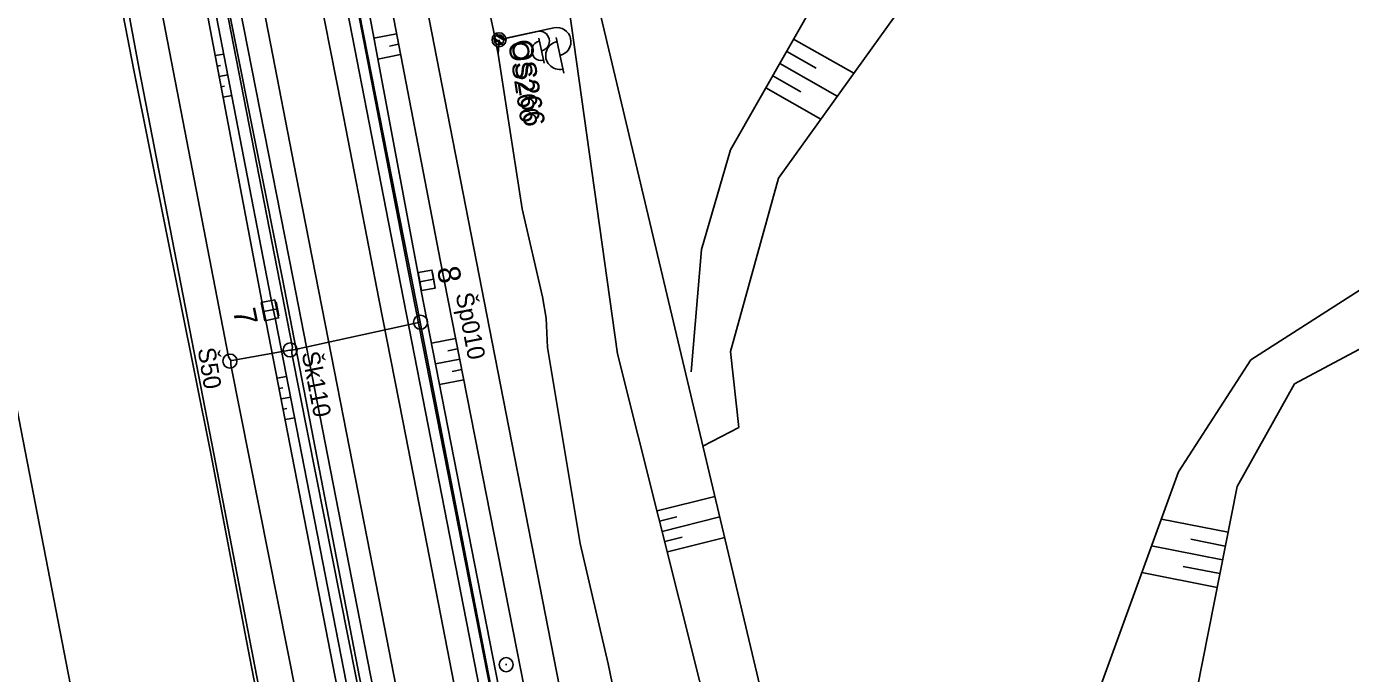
# Model space of a CAD drawing. Extents: x -545967 to -545044, y -1122650 to -1118491.
# Drawn here: x -545804.3 to -545710, y -1118886.3 to -1118840.2 of the extents above; entities that cross this region are included whole.
import ezdxf

# ---------------------------------------------------------------- set-up
doc = ezdxf.new("R2010")
doc.units = 0
for name, color, linetype in [('Vrstva 1', 7, 'Continuous'), ('Vrstva 1 - Koleje', 7, 'Continuous'), ('Vrstva 11 - Trakce', 7, 'Continuous'), ('Vrstva 12 - Trakce zaklady', 7, 'Continuous'), ('Vrstva 25', 7, 'Continuous'), ('Vrstva 25 - silnoproud prvky', 7, 'Continuous'), ('Vrstva 26', 7, 'Continuous'), ('Vrstva 26 - silnoproud', 7, 'Continuous'), ('Vrstva 28 - zabzar', 7, 'Continuous'), ('Vrstva 32', 7, 'Continuous'), ('Vrstva 4 - Teren - stezky - prechody - plochy', 7, 'Continuous'), ('Vrstva 43', 7, 'Continuous'), ('Vrstva 44', 7, 'Continuous'), ('Vrstva 48', 7, 'Continuous'), ('Vrstva 49', 7, 'Continuous'), ('Vrstva 62', 7, 'Continuous'), ('Vrstva 7 - Namezniky-vystroj', 7, 'Continuous')]:
    doc.layers.add(name, color=color, linetype=linetype)

msp = doc.modelspace()

# ---------------------------------------------------------------- linework, layer by layer
at = {"layer": 'Vrstva 1'}
for points in [[(-545803.343, -1118697.361), (-545802.529, -1118701.559), (-545796.372, -1118733.137), (-545788.892, -1118771.626), (-545784.123, -1118796.192), (-545777.723, -1118829.089), (-545771.163, -1118862.699), (-545764.792, -1118895.381), (-545757.603, -1118932.309), (-545753.441, -1118953.648), (-545749.904, -1118971.286), (-545746.403, -1118987.4), (-545742.64, -1119003.664), (-545739.307, -1119017.411), (-545735.997, -1119030.103), (-545730.526, -1119049.438)], [(-545833.035, -1118722.987), (-545832.612, -1118725.218), (-545828.16, -1118748.155), (-545821.787, -1118781.064), (-545814.8, -1118816.973), (-545807.184, -1118856.232), (-545801.349, -1118886.259), (-545795.986, -1118913.812), (-545789.887, -1118945.221), (-545784.095, -1118975.016), (-545776.352, -1119014.883), (-545771.025, -1119042.195)]]:
    msp.add_lwpolyline(points, dxfattribs=at)
at = {"layer": 'Vrstva 1 - Koleje'}
for points in [[(-545789.005, -1118830.866), (-545787.094, -1118840.68), (-545785.112, -1118850.841), (-545782.605, -1118863.702), (-545780.708, -1118873.411), (-545778.842, -1118882.982), (-545777.033, -1118892.261), (-545775.242, -1118901.451), (-545773.471, -1118910.538), (-545771.912, -1118918.507), (-545770.23, -1118927.147), (-545768.195, -1118937.605), (-545766.358, -1118947.027), (-545764.382, -1118957.157), (-545762.439, -1118967.113)], [(-545783.856, -1118835.888), (-545781.902, -1118845.893), (-545780.09, -1118855.197), (-545779.231, -1118859.597), (-545777.534, -1118868.303), (-545775.637, -1118878.025), (-545773.736, -1118887.804), (-545771.983, -1118896.787), (-545770.701, -1118903.363), (-545768.985, -1118912.147), (-545767.842, -1118918.004), (-545766.003, -1118927.456), (-545764.066, -1118937.395), (-545762.038, -1118947.792), (-545760.159, -1118957.414), (-545758.172, -1118967.592)]]:
    msp.add_lwpolyline(points, dxfattribs=at)
at = {"layer": 'Vrstva 11 - Trakce'}
for p, q in [((-545776.407, -1118857.91), (-545776.224, -1118858.893)), ((-545775.424, -1118857.727), (-545775.241, -1118858.71)), ((-545775.332, -1118858.218), (-545776.316, -1118858.402)), ((-545787.536, -1118860.027), (-545787.336, -1118861.007)), ((-545786.556, -1118859.827), (-545786.356, -1118860.807)), ((-545786.456, -1118860.317), (-545787.436, -1118860.517))]:
    msp.add_line(p, q, dxfattribs=at)
at = {"layer": 'Vrstva 12 - Trakce zaklady'}
for p, q in [((-545776.434, -1118857.739), (-545775.451, -1118857.556)), ((-545775.212, -1118858.837), (-545776.195, -1118859.02)), ((-545787.611, -1118859.879), (-545786.631, -1118859.679)), ((-545786.369, -1118860.965), (-545787.349, -1118861.165))]:
    msp.add_line(p, q, dxfattribs=at)
for points in [[(-545776.195, -1118859.02), (-545776.434, -1118857.739), (-545775.451, -1118857.556), (-545775.212, -1118858.837), (-545776.195, -1118859.02)], [(-545776.434, -1118857.739), (-545776.434, -1118857.739), (-545776.195, -1118859.02), (-545776.195, -1118859.02)], [(-545775.451, -1118857.556), (-545775.451, -1118857.556), (-545775.212, -1118858.837), (-545775.212, -1118858.837)], [(-545786.631, -1118859.679), (-545786.369, -1118860.965), (-545787.349, -1118861.165), (-545787.611, -1118859.879), (-545786.631, -1118859.679)], [(-545787.611, -1118859.879), (-545787.611, -1118859.879), (-545787.349, -1118861.165), (-545787.349, -1118861.165)], [(-545786.631, -1118859.679), (-545786.631, -1118859.679), (-545786.369, -1118860.965), (-545786.369, -1118860.965)]]:
    msp.add_lwpolyline(points, dxfattribs=at)
at = {"layer": 'Vrstva 25'}
for p, q in [((-545771.154, -1118841.017), (-545770.349, -1118841.535)), ((-545770.92, -1118840.722), (-545770.18, -1118841.198)), ((-545770.187, -1118841.052), (-545766.766, -1118840.313)), ((-545766.618, -1118840.997), (-545766.069, -1118843.539))]:
    msp.add_line(p, q, dxfattribs=at)
msp.add_circle((-545770.676, -1118841.158), 0.5, dxfattribs=at)
msp.add_circle((-545770.676, -1118841.158), 0.5, dxfattribs=at)
for centre, start, end in [((-545766.555, -1118841.29), 282.19484, 102.19484), ((-545766.356, -1118842.271), 101.49226, 282.89741)]:
    msp.add_arc(centre, 1, start, end, dxfattribs=at)
at = {"layer": 'Vrstva 25 - silnoproud prvky'}
for p, q in [((-545771.01, -1118841.059), (-545770.447, -1118841.422)), ((-545770.847, -1118840.853), (-545770.329, -1118841.186)), ((-545770.334, -1118841.084), (-545767.939, -1118840.567)), ((-545767.836, -1118841.045), (-545767.451, -1118842.824))]:
    msp.add_line(p, q, dxfattribs=at)
msp.add_circle((-545770.676, -1118841.158), 0.35, dxfattribs=at)
for centre, start, end in [((-545767.791, -1118841.251), 282.19484, 102.19484), ((-545767.652, -1118841.937), 101.49226, 282.89741)]:
    msp.add_arc(centre, 0.7, start, end, dxfattribs=at)
at = {"layer": 'Vrstva 26'}
for points in [[(-545746.037, -1118973.539), (-545748.64, -1118961.097), (-545751.402, -1118946.894), (-545751.937, -1118943.575), (-545752.873, -1118933.506), (-545754.741, -1118927.082), (-545757.146, -1118917.51), (-545760.799, -1118898.018), (-545761.246, -1118894.282), (-545761.421, -1118892.823), (-545762.895, -1118885.591), (-545764.903, -1118877.023), (-545767.229, -1118863.082), (-545767.317, -1118860.995), (-545767.592, -1118859.454), (-545769.02, -1118853.189), (-545770.747, -1118842.19), (-545771.097, -1118840.383), (-545773.141, -1118830.925)], [(-545770.747, -1118842.19), (-545770.676, -1118841.158)]]:
    msp.add_lwpolyline(points, dxfattribs=at)
at = {"layer": 'Vrstva 26 - silnoproud'}
for points in [[(-545800.897, -1118821.514), (-545796.684, -1118843.318), (-545791.187, -1118870.631), (-545788.655, -1118883.96), (-545784.722, -1118904.395), (-545780.641, -1118924.894), (-545776.901, -1118944.085), (-545772.527, -1118967.671), (-545767.712, -1118991.461), (-545763.383, -1119013.326), (-545759.751, -1119031.811), (-545755.576, -1119054.337), (-545752.321, -1119069.685), (-545748.72, -1119088.787), (-545745.498, -1119105.777)], [(-545746.037, -1118973.539), (-545748.64, -1118961.097), (-545751.402, -1118946.894), (-545751.937, -1118943.575), (-545752.873, -1118933.506), (-545754.741, -1118927.082), (-545757.146, -1118917.51), (-545760.799, -1118898.018), (-545761.246, -1118894.282), (-545761.421, -1118892.823), (-545762.895, -1118885.591), (-545764.903, -1118877.023), (-545767.229, -1118863.082), (-545767.317, -1118860.995), (-545767.592, -1118859.454), (-545769.02, -1118853.189), (-545770.747, -1118842.19), (-545771.097, -1118840.383), (-545773.141, -1118830.925)], [(-545770.747, -1118842.19), (-545770.676, -1118841.158)]]:
    msp.add_lwpolyline(points, dxfattribs=at)
at = {"layer": 'Vrstva 28 - zabzar'}
msp.add_lwpolyline([(-545759.72, -1119031.91), (-545759.89, -1119030.77), (-545763.23, -1119013.33), (-545766.25, -1118997.62), (-545768.86, -1118984.55), (-545771, -1118974.69), (-545771.8, -1118970.9), (-545773.86, -1118959.07), (-545776.3, -1118946.17), (-545780.31, -1118924.98), (-545785.87, -1118897.11), (-545790.99, -1118870.65), (-545796.29, -1118843.25), (-545799.19, -1118827.63), (-545805.85, -1118794.17), (-545808.2, -1118783.5), (-545812.82, -1118758.82), (-545816.62, -1118739.16), (-545820.43, -1118719.58), (-545822.89, -1118707.67), (-545825.23, -1118696.09)], dxfattribs=at)
at = {"layer": 'Vrstva 32'}
msp.add_lwpolyline([(-545746.9, -1119097.66), (-545750.31, -1119079.79), (-545751.4, -1119074.13), (-545752.97, -1119065.38), (-545755.29, -1119054.49), (-545758.65, -1119036.78), (-545759.72, -1119031.91), (-545759.89, -1119030.77), (-545763.23, -1119013.33), (-545766.25, -1118997.62), (-545768.86, -1118984.55), (-545771, -1118974.69), (-545771.8, -1118970.9), (-545773.86, -1118959.07), (-545776.3, -1118946.17), (-545780.31, -1118924.98), (-545785.87, -1118897.11), (-545790.99, -1118870.65), (-545796.29, -1118843.25), (-545799.19, -1118827.63)], dxfattribs=at)
at = {"layer": 'Vrstva 4 - Teren - stezky - prechody - plochy'}
for points in [[(-545842.991, -1118523.919), (-545841.705, -1118530.396), (-545836.849, -1118554.447), (-545831.054, -1118584.604), (-545819.351, -1118645.264), (-545811.232, -1118686.911), (-545799.532, -1118746.647), (-545788.535, -1118802.768), (-545777.847, -1118857.696), (-545765.826, -1118919.341), (-545755.98, -1118970.183), (-545745.509, -1119023.121), (-545734.813, -1119078.883), (-545723.148, -1119138.675), (-545711.327, -1119199.256), (-545707.51, -1119218.932), (-545706.355, -1119218.803)], [(-545710.225, -1119247.22), (-545719.004, -1119201.386), (-545730.622, -1119141.385), (-545736.208, -1119112.206), (-545742.564, -1119078.927), (-545753.414, -1119021.814), (-545763.359, -1118970.942), (-545773.922, -1118916.709), (-545785.328, -1118858.188), (-545796.206, -1118802.914), (-545806.845, -1118748.63), (-545819.206, -1118686.191), (-545827.818, -1118641.013), (-545849.345, -1118530.249), (-545850.409, -1118525.371)], [(-545711.324, -1119247.435), (-545711.901, -1119243.963), (-545720.224, -1119201.665), (-545721.285, -1119195.757), (-545731.546, -1119141.712), (-545737.081, -1119112.42), (-545743.441, -1119079.103), (-545754.278, -1119022.005), (-545764.127, -1118971.243), (-545774.702, -1118917.119), (-545786.098, -1118858.181), (-545797.005, -1118803.413), (-545807.661, -1118749.422), (-545819.911, -1118686.431), (-545828.531, -1118641.36), (-545850.15, -1118530.525), (-545851.156, -1118525.517)], [(-545787.709, -1118802.92), (-545777.141, -1118857.583), (-545765.122, -1118918.891), (-545755.123, -1118970.549), (-545744.471, -1119024.933), (-545734.117, -1119078.34), (-545722.331, -1119138.405), (-545711.219, -1119196.145), (-545707.543, -1119214.266), (-545707.412, -1119215.197), (-545706.355, -1119218.803)]]:
    msp.add_lwpolyline(points, dxfattribs=at)
at = {"layer": 'Vrstva 43'}
for centre in [(-545776.265, -1118861.272), (-545785.548, -1118863.247), (-545789.837, -1118864.038)]:
    msp.add_circle(centre, 0.5, dxfattribs=at)
at = {"layer": 'Vrstva 44'}
for points in [[(-545785.83, -1118812.749), (-545776.282, -1118861.269), (-545785.186, -1118863.215), (-545785.429, -1118863.254)], [(-545794.86, -1118814.466), (-545785.374, -1118863.065), (-545785.429, -1118863.254)], [(-545799.29, -1118815.321), (-545789.933, -1118863.748), (-545789.78, -1118864.001), (-545789.769, -1118864.308), (-545781.742, -1118904.714), (-545781.69, -1118905.058), (-545781.683, -1118905.37), (-545773.843, -1118945.459), (-545773.731, -1118945.723), (-545773.748, -1118946.113), (-545765.823, -1118986.247), (-545765.769, -1118986.707), (-545765.632, -1118987.212), (-545755.037, -1119039.456), (-545755.013, -1119039.882), (-545755.034, -1119040.218), (-545744.158, -1119093.432), (-545744.096, -1119093.785), (-545744.065, -1119094.166), (-545734.822, -1119146.139)], [(-545766.704, -1118910.666), (-545776.282, -1118861.269)], [(-545785.429, -1118863.254), (-545785.565, -1118863.261), (-545789.56, -1118863.968), (-545789.78, -1118864.001)], [(-545775.683, -1118912.677), (-545785.44, -1118863.505), (-545785.429, -1118863.254)]]:
    msp.add_lwpolyline(points, dxfattribs=at)
at = {"layer": 'Vrstva 48'}
for p, q in [((-545777.968, -1118840.744), (-545779.581, -1118841.055)), ((-545777.826, -1118841.481), (-545778.473, -1118841.605)), ((-545790.884, -1118842.29), (-545790.28, -1118842.176)), ((-545790.744, -1118843.027), (-545790.502, -1118842.981)), ((-545777.685, -1118842.217), (-545779.306, -1118842.529)), ((-545790.604, -1118843.764), (-545789.996, -1118843.648)), ((-545790.465, -1118844.501), (-545790.22, -1118844.454)), ((-545790.325, -1118845.238), (-545789.711, -1118845.121)), ((-545773.769, -1118862.436), (-545775.49, -1118862.775)), ((-545773.624, -1118863.172), (-545774.313, -1118863.308)), ((-545773.479, -1118863.908), (-545775.202, -1118864.247)), ((-545773.334, -1118864.644), (-545774.023, -1118864.78)), ((-545786.477, -1118865.264), (-545785.798, -1118865.132)), ((-545773.189, -1118865.38), (-545774.913, -1118865.719)), ((-545786.334, -1118866), (-545786.062, -1118865.947)), ((-545786.191, -1118866.736), (-545785.512, -1118866.604)), ((-545786.048, -1118867.473), (-545785.776, -1118867.42)), ((-545785.905, -1118868.209), (-545785.225, -1118868.077)), ((-545759.422, -1118874.715), (-545755.301, -1118873.682)), ((-545759.239, -1118875.443), (-545758.006, -1118875.134)), ((-545759.057, -1118876.17), (-545754.954, -1118875.142)), ((-545758.874, -1118876.898), (-545757.646, -1118876.59)), ((-545758.692, -1118877.625), (-545754.608, -1118876.601))]:
    msp.add_line(p, q, dxfattribs=at)
at = {"layer": 'Vrstva 49'}
for points in [[(-545839.308, -1118523.198), (-545838.102, -1118529.579), (-545837.4, -1118533.485), (-545832.706, -1118555.695), (-545825.144, -1118594.377), (-545814.251, -1118651.352), (-545808.026, -1118685.152), (-545795.162, -1118750.192), (-545783.943, -1118809.71), (-545774.848, -1118856.951), (-545763.418, -1118915.038), (-545752.928, -1118968.655), (-545741.707, -1119025.946), (-545730.219, -1119081.986), (-545719.001, -1119141.326), (-545708.857, -1119196.833), (-545704.642, -1119214.146)], [(-545790.558, -1118698.682), (-545783.238, -1118737.17), (-545773.95, -1118795.15), (-545740.894, -1118934.351)], [(-545795.7, -1118699.528), (-545788.233, -1118737.742), (-545783.17, -1118774.198), (-545777.676, -1118791.958), (-545766.252, -1118834.896), (-545762.229, -1118863.517), (-545750.538, -1118910.15), (-545748.755, -1118933.679), (-545738.226, -1118978.242), (-545734.453, -1118993.366), (-545726.802, -1119029.271), (-545708.682, -1119069.733), (-545699.17, -1119099.963), (-545685.313, -1119124.181), (-545683.358, -1119136.056), (-545688.074, -1119145.796), (-545688.341, -1119153.091)], [(-545785.57, -1118809.023), (-545776.461, -1118857.744), (-545776.223, -1118859.028), (-545764.986, -1118916.441), (-545764.658, -1118917.886), (-545754.446, -1118970.66), (-545754.175, -1118971.989), (-545744.319, -1119022.631), (-545744.059, -1119023.95), (-545733.435, -1119078.425), (-545721.625, -1119138.52), (-545721.391, -1119139.742), (-545710.151, -1119197.125), (-545709.969, -1119198.727), (-545706.792, -1119214.135), (-545707.412, -1119215.197), (-545706.355, -1119218.803), (-545705.856, -1119218.828), (-545705.109, -1119218.756), (-545703.505, -1119218.63), (-545703.071, -1119219.321), (-545701.68, -1119223.926)], [(-545712.345, -1119247.635), (-545712.918, -1119244.626), (-545721.552, -1119201.108), (-545732.642, -1119141.942), (-545733.194, -1119140.665), (-545738.437, -1119113.17), (-545744.258, -1119082.787), (-545744.781, -1119080.348), (-545754.155, -1119031.651), (-545755.213, -1119026.18), (-545765.268, -1118974.147), (-545765.5, -1118972.759), (-545775.821, -1118920.177), (-545776.085, -1118918.771), (-545787.25, -1118861.285), (-545787.565, -1118859.78), (-545796.822, -1118811.001)], [(-545711.324, -1119247.435), (-545711.901, -1119243.963), (-545720.224, -1119201.665), (-545721.285, -1119195.757), (-545721.943, -1119195.521), (-545732.082, -1119141.82), (-545732.265, -1119140.515), (-545737.739, -1119112.717), (-545743.315, -1119083.132), (-545744.039, -1119079.561), (-545753.263, -1119031.334), (-545754.002, -1119028.935), (-545754.148, -1119025.929), (-545754.487, -1119024.319), (-545754.825, -1119024.298), (-545764.544, -1118973.992), (-545764.787, -1118972.577), (-545775.108, -1118920.03), (-545775.396, -1118918.541), (-545786.585, -1118861.093), (-545786.924, -1118859.548), (-545796.323, -1118810.897)]]:
    msp.add_lwpolyline(points, dxfattribs=at)
at = {"layer": 'Vrstva 62'}
for points in [[(-545692.811, -1118781.156), (-545700.511, -1118792.986), (-545705.07, -1118798.61), (-545715.862, -1118804.535), (-545726.256, -1118811.927), (-545732.661, -1118819.564), (-545736.865, -1118827.663), (-545739.923, -1118829.641), (-545742.498, -1118829.331), (-545745.615, -1118830.603), (-545744.237, -1118834.28), (-545740.833, -1118837.156), (-545750.78, -1118851.003), (-545754.194, -1118863.365)], [(-545756.99, -1118864.816), (-545756.268, -1118856.102), (-545754.187, -1118849.002), (-545747.945, -1118838.031), (-545749.436, -1118832.786), (-545745.891, -1118827.944), (-545741.576, -1118825.845), (-545739.389, -1118825.489), (-545737.048, -1118819.756), (-545731.429, -1118812.228), (-545724.495, -1118806.644)], [(-545749.698, -1118841.113), (-545745.423, -1118843.545)], [(-545750.193, -1118841.982), (-545748.101, -1118843.172)], [(-545750.688, -1118842.851), (-545746.596, -1118845.179)], [(-545751.182, -1118843.72), (-545749.182, -1118844.858)], [(-545751.677, -1118844.589), (-545747.769, -1118846.812)], [(-545664.463, -1118863.447), (-545693.262, -1118857.214), (-545700.931, -1118857.806), (-545697.393, -1118860.918), (-545700.447, -1118865.244), (-545702.583, -1118858.209), (-545708.513, -1118858.418), (-545717.149, -1118863.96), (-545722.289, -1118871.935), (-545729.33, -1118891.244), (-545724.714, -1118898.613), (-545720.665, -1118904.502), (-545720.365, -1118922.929), (-545725.31, -1118923.845), (-545732.264, -1118918.838), (-545740.824, -1118918.226), (-545744.688, -1118918.372)], [(-545743.949, -1118920.691), (-545740.17, -1118919.261), (-545731.195, -1118920.647), (-545725.86, -1118925.431), (-545718.8, -1118925.214), (-545715.03, -1118928.012), (-545716.07, -1118909.035), (-545717.246, -1118900.828), (-545722.2, -1118893.635), (-545718.125, -1118872.969), (-545714.047, -1118865.665), (-545703.814, -1118860.205), (-545702.609, -1118870.651), (-545693.99, -1118863.27), (-545684.832, -1118860.545), (-545664.047, -1118865.281)], [(-545756.153, -1118870.095), (-545753.595, -1118868.763), (-545754.194, -1118863.365)], [(-545718.768, -1118876.231), (-545723.514, -1118875.295)], [(-545718.962, -1118877.213), (-545721.411, -1118876.729)], [(-545719.155, -1118878.194), (-545724.208, -1118877.197)], [(-545719.349, -1118879.175), (-545721.951, -1118878.661)], [(-545719.542, -1118880.156), (-545724.901, -1118879.099)]]:
    msp.add_lwpolyline(points, dxfattribs=at)
at = {"layer": 'Vrstva 7 - Namezniky-vystroj'}
msp.add_line((-545770.219, -1118885.66), (-545770.119, -1118885.66), dxfattribs=at)
msp.add_circle((-545770.169, -1118885.66), 0.5, dxfattribs=at)

# ---------------------------------------------------------------- texts
at = {"layer": 'Vrstva 11 - Trakce'}
for s, rotation, p in [('8', 280.56834, (-545775.108, -1118857.441)), ('7', 281.51542, (-545789.63, -1118860.44))]:
    msp.add_text(s, height=1.6, rotation=rotation, dxfattribs=at).set_placement(p)
at = {"layer": 'Vrstva 25'}
msp.add_text('OS266', height=1.5, rotation=278.9234, dxfattribs=at).set_placement((-545769.824, -1118841.256))
at = {"layer": 'Vrstva 25 - silnoproud prvky'}
msp.add_text('OS266', height=1.4, rotation=278.9234, dxfattribs=at).set_placement((-545770.03, -1118841.371))
at = {"layer": 'Vrstva 43'}
for s, rotation, p in [('Šp010', 280.99979, (-545773.774, -1118859.28)), ('Š50', 279.31701, (-545792.139, -1118863.178)), ('Šk110', 280.99979, (-545784.738, -1118863.469))]:
    msp.add_text(s, height=1.25, rotation=rotation, dxfattribs=at).set_placement(p)

doc.saveas('drawing.dxf')
